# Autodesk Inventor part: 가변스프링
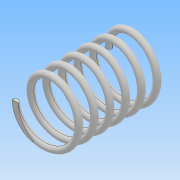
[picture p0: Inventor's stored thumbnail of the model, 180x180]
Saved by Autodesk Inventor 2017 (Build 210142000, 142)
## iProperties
Part Number: 가변스프링
Material: 일반
Document SubType Name: Modeling
Designer: user
Density: 1 g/cm^3
Appearance: 기본값
Mass: 1.051 g
Surface Area: 21.2967 cm^2
Volume: 1.051 cm^3
Author: user
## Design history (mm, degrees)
sketch "스케치1"
  geometry: L1 (-9, 30.5)-(0, 30.5); L2 (0, 30.5)-(0, 0); L3 (0, 0)-(-9, 0); L4 (-9, 0)-(-9, 30.5); C1 r 1 at (-9, 0); 1 further point
  constraints: 8 end point, 2 coincident, 2 parallel, 1 centre point, 1 horizontal, 1 perpendicular
  dimensions: "d0" = 2 diameter of C1; "d1" = 18 diameter of L4 L2; "d2" = 30.5 distance between parallel lines of L3 L1 (derived)
feature "코일1" sketch "스케치1" pitch "d3" = 10; turns "d5" = 6; dims "d4" = 30.5 (= d2), "d6" = 0, angle "d7" = 90 deg, angle "d8" = 90 deg, "d9" = 0, "d10" = 0
sketch "스케치2"
  geometry: L1 (8, 0)-(10, 0) reference; 1 further point
  constraints: 1 horizontal alignment
extrude "돌출1" cut sketch "스케치2" stored distance "d11" = 10; taper "d12" = 0 deg
node "작업 평면1"
sketch "스케치3"
  geometry: L1 (1, 0)-(-1, 0) reference; 1 further point
  constraints: 1 horizontal alignment
extrude "돌출2" cut sketch "스케치3" stored distance "d13" = 10; taper "d14" = 0 deg
node "솔리드1"
node "절단 모서리 투영1"
node "절단 모서리 투영2"
